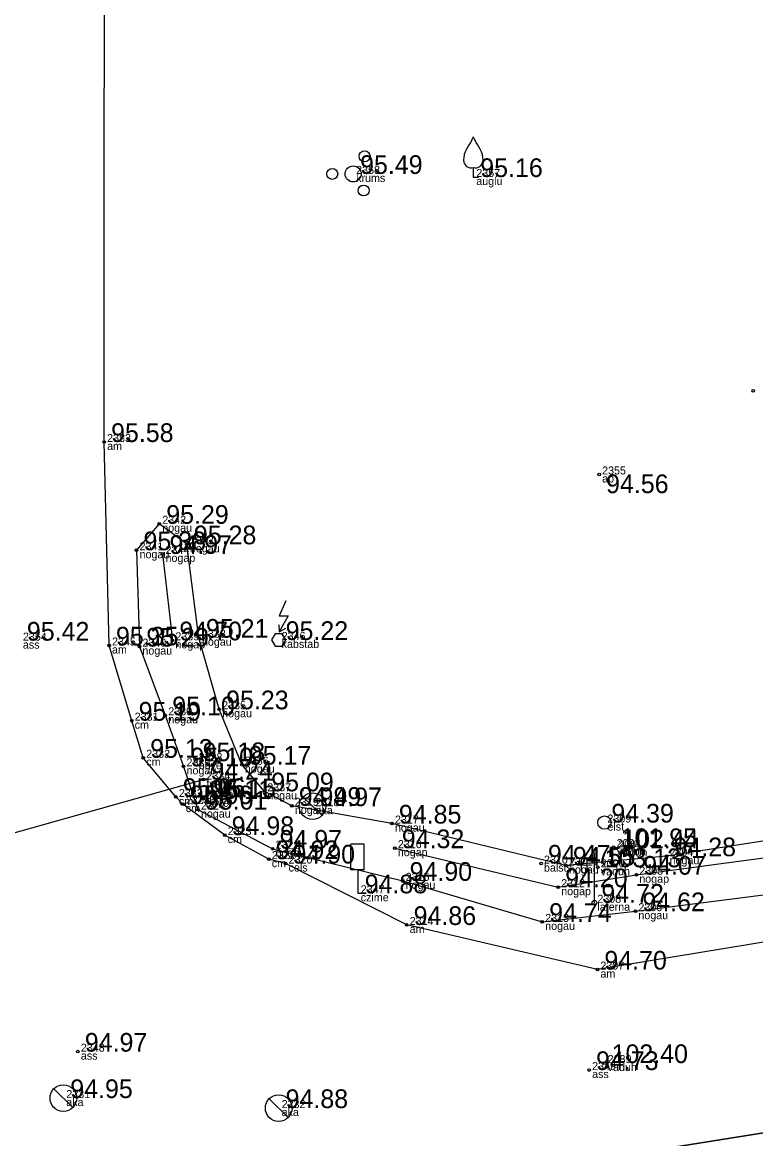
# Model space of a CAD drawing. Extents: x 614911 to 615803, y 262110 to 264311.
# Drawn here: x 615630.27 to 615657.76, y 263599.1 to 263640.94 of the extents above; entities that cross this region are included whole.
import ezdxf

# ---------------------------------------------------------------- set-up
doc = ezdxf.new("R2010")
doc.units = 0
for name, color, linetype in [('Level 1', 7, 'Continuous'), ('Level 11', 7, 'Continuous'), ('Level 12', 7, 'Continuous'), ('Level 16', 7, 'Continuous'), ('Level 18', 7, 'Continuous'), ('Level 31', 7, 'Continuous'), ('Level 37', 7, 'Continuous'), ('Level 44', 7, 'Continuous'), ('Level 53', 7, 'Continuous'), ('Level 54', 7, 'Continuous'), ('Level 57', 7, 'Continuous'), ('Level 58', 7, 'Continuous')]:
    doc.layers.add(name, color=color, linetype=linetype)

msp = doc.modelspace()

# ---------------------------------------------------------------- linework, layer by layer
at = {"layer": 'Level 1'}
for p, q in [((615647.174, 263635.491), (615647.174, 263635.139)), ((615647.174, 263635.139), (615647.374, 263635.139))]:
    msp.add_line(p, q, dxfattribs=at)
for centre, radius in [((615643.097, 263635.915), 0.207), ((615641.886, 263635.255), 0.204), ((615642.67, 263635.255), 0.301), ((615643.065, 263634.635), 0.205)]:
    msp.add_circle(centre, radius, dxfattribs=at)
for centre, radius, start, end in [((615659.799, 263628.743), 14.88, 148.4844, 149.9901), ((615646.757, 263636.777), 0.439, 324.3837, 341.712), ((615647.591, 263636.777), 0.439, 198.288, 215.6163), ((615634.549, 263628.743), 14.88, 30.0099, 31.5156), ((615647.698, 263635.764), 0.89, 151.757, 179.9138), ((615646.65, 263635.764), 0.89, 0.0862, 28.243), ((615647.098, 263635.77), 0.29, 181.0782, 285.2823), ((615647.25, 263635.77), 0.29, 254.7177, 358.9218)]:
    msp.add_arc(centre, radius, start, end, dxfattribs=at)
at = {"layer": 'Level 11'}
msp.add_line((615625.244, 263609.235), (615637.058, 263612.559), dxfattribs=at)
at = {"layer": 'Level 12'}
for p, q in [((615639.902, 263618.091), (615640.143, 263618.23)), ((615640.789, 263611.911), (615641.507, 263611.215)), ((615631.448, 263600.972), (615632.166, 263600.276)), ((615639.519, 263600.598), (615640.237, 263599.902))]:
    msp.add_line(p, q, dxfattribs=at)
for points in [[(615640.151, 263619.253), (615639.902, 263618.69), (615640.238, 263618.69), (615639.902, 263618.091)], [(615639.88, 263618.361), (615639.902, 263618.091)]]:
    msp.add_lwpolyline(points, dxfattribs=at)
msp.add_lwpolyline([(615639.746, 263617.561), (615640.012, 263617.561), (615640.145, 263617.791), (615640.012, 263618.022), (615639.746, 263618.022), (615639.613, 263617.791)], close=True, dxfattribs=at)
for centre in [(615641.148, 263611.563), (615631.807, 263600.624), (615639.878, 263600.25)]:
    msp.add_circle(centre, 0.5, dxfattribs=at)
at = {"layer": 'Level 16'}
for p, q in [((615643.088, 263610.145), (615642.588, 263610.145)), ((615642.588, 263609.176), (615642.588, 263610.145)), ((615643.088, 263609.176), (615643.088, 263610.145)), ((615643.088, 263609.176), (615642.588, 263609.176)), ((615642.842, 263609.176), (615642.842, 263608.298)), ((615642.842, 263608.298), (615643.157, 263608.298))]:
    msp.add_line(p, q, dxfattribs=at)
at = {"layer": 'Level 18'}
msp.add_circle((615652.088, 263610.949), 0.25, dxfattribs=at)
at = {"layer": 'Level 31'}
msp.add_line((615635.526, 263621.016), (615635.896, 263617.777), dxfattribs=at)
for points in [[(615635.404, 263622.144), (615634.552, 263621.153), (615634.659, 263617.543), (615635.629, 263614.969), (615636.312, 263613.055), (615636.853, 263611.434), (615639.652, 263609.969), (615644.526, 263608.765), (615649.756, 263607.226), (615653.25, 263607.628), (615664.615, 263609.073), (615674.696, 263611.23), (615683.275, 263614.206)], [(615683.652, 263616.52), (615682.987, 263617.038), (615670.657, 263613.92), (615664.599, 263611.281), (615654.418, 263609.687), (615650.647, 263609.338), (615644.124, 263610.911), (615640.372, 263611.576), (615639.339, 263612.12), (615638.498, 263613.119), (615637.649, 263615.194), (615636.891, 263617.877), (615636.439, 263621.377), (615635.404, 263622.144)], [(615644.233, 263609.989), (615650.357, 263608.527), (615653.284, 263608.995), (615664.696, 263610.518), (615674.177, 263612.977), (615683.523, 263616.209)], [(615680.313, 263602.397), (615679.358, 263603.382), (615677.12, 263603.454), (615669.019, 263601.376), (615659.382, 263599.532), (615651.478, 263598.277), (615647.143, 263595.409), (615645.002, 263589.292)]]:
    msp.add_lwpolyline(points, dxfattribs=at)
at = {"layer": 'Level 37'}
for points in [[(615689.749, 263618.823), (615688.82, 263614.514), (615674.927, 263610.554), (615664.21, 263607.477), (615651.825, 263605.439), (615644.676, 263607.111), (615640.138, 263609.414), (615639.508, 263609.578), (615637.855, 263610.48), (615636.285, 263611.639), (615636.027, 263611.907), (615634.803, 263613.377), (615634.369, 263614.767), (615633.519, 263617.584), (615633.336, 263625.21), (615633.344, 263651.772), (615633.393, 263671.43), (615633.395, 263690.2), (615635.468, 263691.528), (615641.886, 263693.128), (615652.363, 263692.83)], [(615622.954, 263597.67), (615628.907, 263597.13), (615631.65, 263596.73), (615651.478, 263598.277), (615659.382, 263599.532), (615671.586, 263602.535), (615680.056, 263604.519), (615682.925, 263605.355), (615694.583, 263609.208), (615696.467, 263609.569)]]:
    msp.add_lwpolyline(points, dxfattribs=at)
at = {"layer": 'Level 44'}
for p, q in [((615651.713, 263607.944), (615651.713, 263609.827)), ((615651.713, 263609.607), (615651.078, 263609.607)), ((615651.213, 263609.607), (615651.213, 263609.215)), ((615651.423, 263609.607), (615651.423, 263609.215))]:
    msp.add_line(p, q, dxfattribs=at)
msp.add_circle((615651.713, 263607.944), 0.09, dxfattribs=at)
msp.add_ellipse((615651.318, 263609.215), major_axis=(0, 0.151), ratio=0.695971, start_param=1.570796, end_param=4.712389, dxfattribs=at)
at = {"layer": 'Level 57'}
for centre in [(615657.668, 263627.128), (615633.336, 263625.21), (615651.89, 263623.993), (615635.404, 263622.144), (615634.552, 263621.153), (615635.526, 263621.016), (615636.439, 263621.377), (615635.896, 263617.777), (615636.891, 263617.877), (615633.519, 263617.584), (615634.659, 263617.543), (615637.649, 263615.194), (615634.369, 263614.767), (615635.629, 263614.969), (615634.803, 263613.377), (615636.312, 263613.055), (615636.768, 263613.249), (615638.498, 263613.119), (615637.058, 263612.559), (615636.027, 263611.907), (615637.025, 263611.837), (615637.17, 263611.897), (615639.339, 263612.12), (615636.285, 263611.639), (615636.853, 263611.434), (615640.372, 263611.576), (615644.124, 263610.911), (615637.855, 263610.48), (615639.652, 263609.969), (615644.233, 263609.989), (615652.434, 263610.03), (615652.492, 263609.978), (615654.418, 263609.687), (615639.508, 263609.578), (615640.138, 263609.414), (615649.711, 263609.411), (615650.647, 263609.338), (615651.839, 263609.273), (615653.284, 263608.995), (615644.526, 263608.765), (615650.357, 263608.527), (615653.25, 263607.628), (615649.756, 263607.226), (615644.676, 263607.111), (615651.825, 263605.439), (615632.352, 263602.364), (615652.097, 263601.936), (615651.514, 263601.675)]:
    msp.add_circle(centre, 0.05, dxfattribs=at)
at = {"layer": 'Level 58'}
for centre in [(615657.668, 263627.128), (615633.336, 263625.21), (615651.89, 263623.993), (615635.404, 263622.144), (615634.552, 263621.153), (615635.526, 263621.016), (615636.439, 263621.377), (615635.896, 263617.777), (615636.891, 263617.877), (615633.519, 263617.584), (615634.659, 263617.543), (615637.649, 263615.194), (615634.369, 263614.767), (615635.629, 263614.969), (615634.803, 263613.377), (615636.312, 263613.055), (615636.768, 263613.249), (615638.498, 263613.119), (615637.058, 263612.559), (615636.027, 263611.907), (615637.025, 263611.837), (615637.17, 263611.897), (615639.339, 263612.12), (615636.285, 263611.639), (615636.853, 263611.434), (615640.372, 263611.576), (615644.124, 263610.911), (615637.855, 263610.48), (615639.652, 263609.969), (615644.233, 263609.989), (615652.434, 263610.03), (615652.492, 263609.978), (615654.418, 263609.687), (615639.508, 263609.578), (615640.138, 263609.414), (615649.711, 263609.411), (615650.647, 263609.338), (615651.839, 263609.273), (615653.284, 263608.995), (615644.526, 263608.765), (615650.357, 263608.527), (615653.25, 263607.628), (615649.756, 263607.226), (615644.676, 263607.111), (615651.825, 263605.439), (615632.352, 263602.364), (615652.097, 263601.936), (615651.514, 263601.675)]:
    msp.add_circle(centre, 0.05, dxfattribs=at)

# ---------------------------------------------------------------- texts
at = {"layer": 'Level 53'}
for s, p in [(' krums', (615642.67, 263634.955)), (' auglu', (615647.174, 263634.839)), (' am', (615633.336, 263624.91)), (' ap', (615651.89, 263623.693)), (' nogau', (615635.404, 263621.844)), (' nogau', (615634.552, 263620.853)), (' nogau', (615636.439, 263621.077)), (' nogap', (615635.526, 263620.716)), (' ass', (615630.18, 263617.467)), (' nogap', (615635.896, 263617.477)), (' nogau', (615636.891, 263617.577)), (' kabstab', (615639.879, 263617.491)), (' am', (615633.519, 263617.284)), (' nogau', (615634.659, 263617.243)), (' nogau', (615635.629, 263614.669)), (' nogau', (615637.649, 263614.894)), (' cm', (615634.369, 263614.467)), (' cm', (615634.803, 263613.077)), (' buve', (615636.768, 263612.949)), (' nogau', (615636.312, 263612.755)), (' nogau', (615638.498, 263612.819)), (' tekne', (615637.058, 263612.259)), (' cm', (615636.027, 263611.607)), (' buve', (615637.025, 263611.537)), (' buve', (615637.17, 263611.597)), (' nogau', (615639.339, 263611.82)), (' cm', (615636.285, 263611.339)), (' nogau', (615640.372, 263611.276)), (' aka', (615641.148, 263611.263)), (' nogau', (615636.853, 263611.134)), (' nogau', (615644.124, 263610.611)), (' elst', (615652.088, 263610.649)), (' cm', (615637.855, 263610.18)), (' nogau', (615639.652, 263609.669)), (' nogap', (615644.233, 263609.689)), (' vaduh', (615652.434, 263609.73)), (' vaduh', (615652.492, 263609.678)), (' cm', (615639.508, 263609.278)), (' cels', (615640.138, 263609.114)), (' balsts', (615649.711, 263609.111)), (' nogau', (615654.418, 263609.387)), (' nogau', (615650.647, 263609.038)), (' vaduh', (615651.839, 263608.973)), (' nogap', (615653.284, 263608.695)), (' nogau', (615644.526, 263608.465)), (' czime', (615642.842, 263607.998)), (' nogap', (615650.357, 263608.227)), (' laterna', (615651.713, 263607.644)), (' nogau', (615653.25, 263607.328)), (' am', (615644.676, 263606.811)), (' nogau', (615649.756, 263606.926)), (' am', (615651.825, 263605.139)), (' ass', (615632.352, 263602.064)), (' vaduh', (615652.097, 263601.636)), (' ass', (615651.514, 263601.375)), (' aka', (615631.807, 263600.324)), (' aka', (615639.878, 263599.95))]:
    msp.add_text(s, height=0.3, dxfattribs=at).set_placement(p)
at = {"layer": 'Level 54'}
for s, p in [(' 2358', (615642.67, 263635.255)), (' 2357', (615647.174, 263635.139)), (' 2383', (615633.336, 263625.21)), (' 2355', (615651.89, 263623.993)), (' 2342', (615635.404, 263622.144)), (' 2341', (615634.552, 263621.153)), (' 2343', (615636.439, 263621.377)), (' 2344', (615635.526, 263621.016)), (' 2338', (615636.891, 263617.877)), (' 2354', (615630.18, 263617.767)), (' 2345', (615633.519, 263617.584)), (' 2340', (615634.659, 263617.543)), (' 2339', (615635.896, 263617.777)), (' 2346', (615639.879, 263617.791)), (' 2330', (615635.629, 263614.969)), (' 2335', (615637.649, 263615.194)), (' 2331', (615634.369, 263614.767)), (' 2332', (615634.803, 263613.377)), (' 2328', (615636.768, 263613.249)), (' 2329', (615636.312, 263613.055)), (' 2336', (615638.498, 263613.119)), (' 2334', (615637.058, 263612.559)), (' 2337', (615639.339, 263612.12)), (' 2333', (615636.027, 263611.907)), (' 2325', (615636.285, 263611.639)), (' 2327', (615637.025, 263611.837)), (' 2326', (615637.17, 263611.897)), (' 2319', (615640.372, 263611.576)), (' 2318', (615641.148, 263611.563)), (' 2324', (615636.853, 263611.434)), (' 2317', (615644.124, 263610.911)), (' 2309', (615652.088, 263610.949)), (' 2323', (615637.855, 263610.48)), (' 2321', (615639.652, 263609.969)), (' 2316', (615644.233, 263609.989)), (' 2092', (615652.434, 263610.03)), (' 2091', (615652.492, 263609.978)), (' 2322', (615639.508, 263609.578)), (' 2304', (615654.418, 263609.687)), (' 2320', (615640.138, 263609.414)), (' 2310', (615649.711, 263609.411)), (' 2311', (615650.647, 263609.338)), (' 2090', (615651.839, 263609.273)), (' 2315', (615644.526, 263608.765)), (' 2305', (615653.284, 263608.995)), (' 2347', (615642.842, 263608.298)), (' 2312', (615650.357, 263608.527)), (' 2308', (615651.713, 263607.944)), (' 2306', (615653.25, 263607.628)), (' 2314', (615644.676, 263607.111)), (' 2313', (615649.756, 263607.226)), (' 2307', (615651.825, 263605.439)), (' 2348', (615632.352, 263602.364)), (' 2089', (615652.097, 263601.936)), (' 2349', (615651.514, 263601.675)), (' 2231', (615631.807, 263600.624)), (' 2232', (615639.878, 263600.25))]:
    msp.add_text(s, height=0.3, dxfattribs=at).set_placement(p)
at = {"layer": 'Level 58'}
for s, p in [(' 95.49', (615642.67, 263635.255)), (' 95.16', (615647.174, 263635.139)), (' 95.58', (615633.336, 263625.21)), (' 94.56', (615651.89, 263623.293)), (' 95.29', (615635.404, 263622.144)), (' 95.38', (615634.552, 263621.153)), (' 95.28', (615636.439, 263621.377)), (' 94.97', (615635.526, 263621.016)), (' 95.21', (615636.891, 263617.877)), (' 95.42', (615630.18, 263617.767)), (' 95.35', (615633.519, 263617.584)), (' 95.29', (615634.659, 263617.543)), (' 94.70', (615635.896, 263617.777)), (' 95.22', (615639.879, 263617.791)), (' 95.10', (615635.629, 263614.969)), (' 95.23', (615637.649, 263615.194)), (' 95.19', (615634.369, 263614.767)), (' 95.13', (615634.803, 263613.377)), (' 95.18', (615636.768, 263613.249)), (' 95.10', (615636.312, 263613.055)), (' 95.17', (615638.498, 263613.119)), (' 94.24', (615637.058, 263612.559)), (' 95.09', (615639.339, 263612.12)), (' 95.06', (615636.027, 263611.907)), (' 95.06', (615636.285, 263611.639)), (' 95.11', (615637.025, 263611.837)), (' 95.15', (615637.17, 263611.897)), (' 94.99', (615640.372, 263611.576)), (' 94.97', (615641.148, 263611.563)), (' 95.01', (615636.853, 263611.434)), (' 94.85', (615644.124, 263610.911)), (' 94.39', (615652.088, 263610.949)), (' 94.98', (615637.855, 263610.48)), (' 94.97', (615639.652, 263609.969)), (' 94.32', (615644.233, 263609.989)), (' 101.95', (615652.434, 263610.03)), (' 102.44', (615652.492, 263609.978)), (' 94.92', (615639.508, 263609.578)), (' 94.28', (615654.418, 263609.687)), (' 94.90', (615640.138, 263609.414)), (' 94.47', (615649.711, 263609.411)), (' 94.55', (615650.647, 263609.338)), (' 103.13', (615651.839, 263609.273)), (' 94.90', (615644.526, 263608.765)), (' 94.07', (615653.284, 263608.995)), (' 94.88', (615642.842, 263608.298)), (' 94.20', (615650.357, 263608.527)), (' 94.72', (615651.713, 263607.944)), (' 94.62', (615653.25, 263607.628)), (' 94.86', (615644.676, 263607.111)), (' 94.74', (615649.756, 263607.226)), (' 94.70', (615651.825, 263605.439)), (' 94.97', (615632.352, 263602.364)), (' 102.40', (615652.097, 263601.936)), (' 94.73', (615651.514, 263601.675)), (' 94.95', (615631.807, 263600.624)), (' 94.88', (615639.878, 263600.25))]:
    msp.add_text(s, height=0.7, dxfattribs=at).set_placement(p)

doc.saveas('drawing.dxf')
